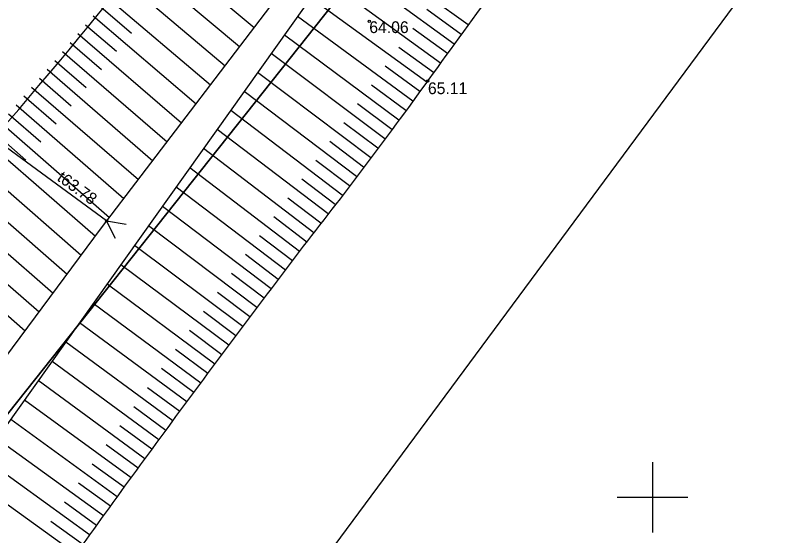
# Model space of a CAD drawing. Extents: x 616607 to 617499, y 408385 to 409695.
# Drawn here: x 617272.92 to 617306.12, y 409448.38 to 409470.48 of the extents above; entities that cross this region are included whole.
import ezdxf

# ---------------------------------------------------------------- set-up
doc = ezdxf.new("R2010")
doc.units = 0
for name, color, linetype in [('DREN_ELEM_####_####_#', 7, 'Continuous'), ('DREN_VADP_####_####_#', 7, 'Continuous'), ('DREN_VADP_####_TKST_#', 7, 'Continuous'), ('GEOD_ELEM_####_####_#', 7, 'Continuous'), ('HIDG_GRAV_####_####_#', 7, 'Continuous'), ('RAMI_UZMR_####_####_#', 7, 'Continuous'), ('RELJ_AATZ_####_TKST_#', 7, 'Continuous'), ('RELJ_ELEM_####_####_#', 7, 'Continuous'), ('RELJ_NOGA_####_####_#', 7, 'Continuous'), ('ROBZ_PROJ_####_####_#', 7, 'Continuous'), ('ROBZ_UZMR_####_####_#', 7, 'Continuous')]:
    doc.layers.add(name, color=color, linetype=linetype)

# ---------------------------------------------------------------- blocks, each defined once
blk = doc.blocks.new('PKT')
at = {"layer": 'RELJ_ELEM_####_####_#'}
blk.add_circle((0, 0), 0.05, dxfattribs=at)
blk = doc.blocks.new('DRIZVA')
at = {"layer": 'DREN_ELEM_####_####_#'}
blk.add_lwpolyline([(0.75, -0.375), (0, 0), (0.75, 0.375)], dxfattribs=at)
blk = doc.blocks.new('KRUSTS')
at = {"layer": 'GEOD_ELEM_####_####_#'}
for p, q in [((0, 1.5), (0, 0)), ((-1.5, 0), (0, 0)), ((0, 0), (0, -1.5)), ((0, 0), (1.5, 0))]:
    blk.add_line(p, q, dxfattribs=at)

msp = doc.modelspace()

# ---------------------------------------------------------------- linework, layer by layer
at = {"layer": 'DREN_VADP_####_####_#'}
msp.add_lwpolyline([(617276.789, 409461.747), (617266.774, 409469.076)], dxfattribs=at)
at = {"layer": 'HIDG_GRAV_####_####_#'}
for points in [[(617196.049, 409072.553), (617193.886, 409072.979), (617195.921, 409087.874), (617195.921, 409087.874), (617199.518, 409112.516), (617194.569, 409134.842), (617162.019, 409207.474), (617151.93, 409229.107), (617149.428, 409241.28), (617152.359, 409253.938), (617188.564, 409303.055), (617197.968, 409312.659), (617223.456, 409346.169), (617232.567, 409363.51), (617247.671, 409422.509), (617276.576, 409461.456), (617285.007, 409472.526), (617327.765, 409527.3)], [(617198.671, 409072.074), (617200.929, 409072.435), (617202.532, 409075.622), (617201.237, 409087.874), (617202.422, 409112.516), (617197.415, 409136.544), (617162.613, 409207.758), (617153.021, 409229.447), (617150.525, 409241.262), (617153.298, 409253.658), (617189.431, 409302.264), (617198.754, 409312.12), (617224.478, 409345.652), (617234.105, 409363.027), (617250.009, 409421.44), (617285.914, 409471.848), (617328.6, 409526.531)]]:
    msp.add_lwpolyline(points, dxfattribs=at)
at = {"layer": 'RAMI_UZMR_####_####_#'}
msp.add_lwpolyline([(617101.571, 408748.246), (617213.472, 409074.039), (617215.883, 409140.56), (617165.121, 409241.478), (617252.137, 409353.424), (617269.572, 409425.099), (617332.631, 409510.312), (617439.945, 409622.037), (617425.373, 409635.959), (617242.079, 409440.82), (617216.614, 409355.716), (617136.613, 409246.751), (617191.828, 409115.62), (617145.545, 408952.8)], dxfattribs=at)
at = {"layer": 'RELJ_NOGA_####_####_#'}
for p, q in [((617278.791, 409473.527), (617283.066, 409469.978)), ((617292.163, 409470.078), (617287.288, 409473.608)), ((617278.15, 409472.76), (617282.445, 409469.162)), ((617291.576, 409469.268), (617286.674, 409472.822)), ((617277.506, 409471.995), (617281.825, 409468.347)), ((617290.989, 409468.458), (617286.059, 409472.034)), ((617276.86, 409471.232), (617281.208, 409467.537)), ((617290.402, 409467.649), (617285.476, 409471.233)), ((617276.536, 409470.851), (617277.845, 409469.735)), ((617291.869, 409469.673), (617290.402, 409470.735)), ((617276.211, 409470.47), (617276.211, 409470.471)), ((617276.211, 409470.47), (617280.591, 409466.727)), ((617289.812, 409466.841), (617284.911, 409470.44)), ((617275.886, 409470.09), (617275.886, 409470.09)), ((617275.886, 409470.09), (617277.205, 409468.96)), ((617292.163, 409470.078), (617292.163, 409470.077)), ((617275.561, 409469.711), (617275.56, 409469.711)), ((617275.561, 409469.711), (617279.979, 409465.924)), ((617289.218, 409466.037), (617284.349, 409469.652)), ((617291.282, 409468.863), (617289.808, 409469.932)), ((617291.869, 409469.673), (617291.87, 409469.672)), ((617275.235, 409469.331), (617275.235, 409469.332)), ((617275.235, 409469.331), (617276.566, 409468.188)), ((617290.695, 409468.053), (617289.215, 409469.127)), ((617291.576, 409469.268), (617291.577, 409469.267)), ((617274.909, 409468.953), (617274.908, 409468.953)), ((617274.909, 409468.953), (617279.362, 409465.113)), ((617288.621, 409465.235), (617283.785, 409468.86)), ((617291.282, 409468.863), (617291.283, 409468.863)), ((617274.582, 409468.574), (617274.582, 409468.574)), ((617274.582, 409468.574), (617275.924, 409467.414)), ((617290.107, 409467.245), (617288.633, 409468.322)), ((617290.989, 409468.458), (617290.99, 409468.458)), ((617274.255, 409468.196), (617274.255, 409468.196)), ((617274.255, 409468.196), (617278.75, 409464.31)), ((617288.02, 409464.435), (617283.212, 409468.055)), ((617290.695, 409468.053), (617290.696, 409468.053)), ((617273.928, 409467.818), (617273.928, 409467.818)), ((617273.928, 409467.818), (617275.282, 409466.644)), ((617273.601, 409467.44), (617273.6, 409467.44)), ((617273.601, 409467.44), (617278.139, 409463.507)), ((617289.515, 409466.439), (617288.049, 409467.52)), ((617290.402, 409467.649), (617290.403, 409467.648)), ((617273.273, 409467.062), (617273.273, 409467.062)), ((617273.273, 409467.062), (617274.64, 409465.874)), ((617287.418, 409463.637), (617282.642, 409467.254)), ((617290.107, 409467.245), (617290.108, 409467.244)), ((617272.945, 409466.685), (617272.944, 409466.685)), ((617272.945, 409466.685), (617277.524, 409462.7)), ((617288.92, 409465.635), (617287.463, 409466.72)), ((617289.812, 409466.841), (617289.813, 409466.841)), ((617286.813, 409462.84), (617282.069, 409466.45)), ((617289.515, 409466.439), (617289.516, 409466.438)), ((617272.617, 409466.308), (617273.998, 409465.106)), ((617289.218, 409466.037), (617289.219, 409466.036)), ((617272.288, 409465.931), (617276.914, 409461.899)), ((617288.321, 409464.835), (617286.873, 409465.92)), ((617271.96, 409465.554), (617273.355, 409464.338)), ((617286.208, 409462.044), (617281.492, 409465.639)), ((617288.92, 409465.635), (617288.92, 409465.635)), ((617271.631, 409465.177), (617276.309, 409461.096)), ((617287.719, 409464.036), (617286.282, 409465.122)), ((617288.621, 409465.235), (617288.621, 409465.234)), ((617285.601, 409461.249), (617280.911, 409464.824)), ((617288.321, 409464.835), (617288.321, 409464.834)), ((617270.974, 409464.423), (617275.711, 409460.29)), ((617288.02, 409464.435), (617288.021, 409464.434)), ((617284.995, 409460.454), (617280.33, 409464.008)), ((617287.116, 409463.238), (617285.688, 409464.322)), ((617287.719, 409464.036), (617287.719, 409464.036)), ((617270.316, 409463.67), (617275.113, 409459.484)), ((617286.511, 409462.442), (617285.091, 409463.522)), ((617287.418, 409463.637), (617287.418, 409463.636)), ((617284.39, 409459.658), (617279.745, 409463.188)), ((617287.116, 409463.238), (617287.116, 409463.238)), ((617269.659, 409462.916), (617274.515, 409458.679)), ((617285.905, 409461.647), (617284.494, 409462.722)), ((617286.813, 409462.84), (617286.814, 409462.84)), ((617283.785, 409458.862), (617279.16, 409462.366)), ((617286.511, 409462.442), (617286.511, 409462.442)), ((617269.002, 409462.162), (617273.921, 409457.878)), ((617286.208, 409462.044), (617286.209, 409462.044)), ((617285.298, 409460.851), (617283.895, 409461.921)), ((617268.345, 409461.408), (617273.326, 409457.077)), ((617283.182, 409458.064), (617278.571, 409461.539)), ((617285.905, 409461.647), (617285.905, 409461.647)), ((617284.692, 409460.056), (617283.297, 409461.119)), ((617285.601, 409461.249), (617285.602, 409461.248)), ((617282.581, 409457.265), (617277.979, 409460.708)), ((617285.298, 409460.851), (617285.299, 409460.851)), ((617284.995, 409460.454), (617284.996, 409460.453)), ((617284.087, 409459.26), (617282.697, 409460.316)), ((617284.692, 409460.056), (617284.693, 409460.056)), ((617281.982, 409456.464), (617277.393, 409459.885)), ((617283.483, 409458.463), (617282.098, 409459.51)), ((617284.39, 409459.658), (617284.39, 409459.658)), ((617281.385, 409455.662), (617276.808, 409459.064)), ((617284.087, 409459.26), (617284.087, 409459.26)), ((617282.881, 409457.665), (617281.499, 409458.703)), ((617283.785, 409458.862), (617283.786, 409458.861)), ((617283.483, 409458.463), (617283.483, 409458.463)), ((617280.789, 409454.858), (617276.22, 409458.239)), ((617283.182, 409458.064), (617283.182, 409458.064)), ((617282.281, 409456.865), (617280.903, 409457.895)), ((617280.195, 409454.054), (617275.637, 409457.419)), ((617282.881, 409457.665), (617282.881, 409457.665)), ((617281.683, 409456.063), (617280.308, 409457.085)), ((617282.581, 409457.265), (617282.581, 409457.264)), ((617282.281, 409456.865), (617282.281, 409456.864)), ((617279.602, 409453.249), (617275.05, 409456.596)), ((617281.982, 409456.464), (617281.983, 409456.463)), ((617281.087, 409455.26), (617279.715, 409456.277)), ((617281.683, 409456.063), (617281.684, 409456.063)), ((617279.009, 409452.443), (617274.467, 409455.778)), ((617280.492, 409454.456), (617279.123, 409455.469)), ((617281.385, 409455.662), (617281.386, 409455.661)), ((617281.087, 409455.26), (617281.087, 409455.26)), ((617278.419, 409451.637), (617273.883, 409454.958)), ((617280.789, 409454.858), (617280.79, 409454.858)), ((617279.898, 409453.652), (617278.532, 409454.659)), ((617280.492, 409454.456), (617280.492, 409454.456)), ((617277.829, 409450.829), (617273.295, 409454.131)), ((617280.195, 409454.054), (617280.196, 409454.054)), ((617279.305, 409452.846), (617277.941, 409453.848)), ((617279.898, 409453.652), (617279.898, 409453.652)), ((617277.24, 409450.02), (617272.711, 409453.312)), ((617279.602, 409453.249), (617279.602, 409453.249)), ((617278.714, 409452.04), (617277.352, 409453.038)), ((617279.305, 409452.846), (617279.306, 409452.846)), ((617276.653, 409449.211), (617272.124, 409452.488)), ((617279.009, 409452.443), (617279.01, 409452.443)), ((617278.124, 409451.233), (617276.763, 409452.226)), ((617278.714, 409452.04), (617278.714, 409452.04)), ((617276.067, 409448.401), (617271.54, 409451.668)), ((617277.535, 409450.425), (617276.176, 409451.415)), ((617278.419, 409451.637), (617278.419, 409451.636)), ((617278.124, 409451.233), (617278.124, 409451.233)), ((617275.482, 409447.59), (617270.957, 409450.849)), ((617277.829, 409450.829), (617277.83, 409450.828)), ((617276.947, 409449.616), (617275.588, 409450.601)), ((617277.535, 409450.425), (617277.535, 409450.425)), ((617276.36, 409448.806), (617275.002, 409449.788)), ((617277.24, 409450.02), (617277.241, 409450.02)), ((617276.947, 409449.616), (617276.947, 409449.616)), ((617276.653, 409449.211), (617276.654, 409449.211)), ((617275.774, 409447.995), (617274.417, 409448.975)), ((617276.36, 409448.806), (617276.36, 409448.806)), ((617276.067, 409448.401), (617276.068, 409448.4))]:
    msp.add_line(p, q, dxfattribs=at)
for points in [[(617148.095, 409250.281), (617149.367, 409254.282), (617150.639, 409258.284), (617151.912, 409262.285), (617156.597, 409277.022), (617171.021, 409286.603), (617180.379, 409298.915), (617194.802, 409317.89), (617212.921, 409334.355), (617223.034, 409356.295), (617225.913, 409362.541), (617226.817, 409369.327), (617228.782, 409375.821), (617233.86, 409392.605), (617237.843, 409409.628), (617244.376, 409426.063), (617252.258, 409445.895), (617268.673, 409460.708), (617281.86, 409477.296), (617294.583, 409493.301), (617307.725, 409508.821), (617320.496, 409524.825), (617320.543, 409524.885), (617320.584, 409524.948), (617320.623, 409525.013), (617320.843, 409525.374), (617320.906, 409525.909), (617320.728, 409526.275), (617320.636, 409526.463), (617320.388, 409526.567), (617320.294, 409526.764), (617319.61, 409528.184), (617318.926, 409529.604), (617318.242, 409531.024)], [(617336.806, 409523.735), (617334.087, 409521.174), (617331.368, 409518.613), (617328.65, 409516.053), (617321.193, 409509.03), (617314.57, 409501.094), (617308.568, 409492.793), (617305.546, 409488.614), (617302.537, 409484.426), (617299.516, 409480.247), (617296.49, 409476.063), (617293.469, 409471.875), (617290.436, 409467.695), (617287.772, 409464.025), (617284.965, 409460.461), (617282.252, 409456.826), (617279.55, 409453.205), (617276.887, 409449.558), (617274.256, 409445.882), (617271.624, 409442.206), (617269.17, 409438.414), (617266.782, 409434.573), (617265.581, 409432.642), (617264.455, 409430.674), (617263.346, 409428.69), (617262.228, 409426.69), (617261.169, 409424.668), (617260.166, 409422.606), (617258.56, 409419.302), (617257.132, 409415.931), (617255.903, 409412.47), (617254.682, 409409.035), (617253.531, 409405.585), (617252.579, 409402.073), (617251.627, 409398.563), (617250.683, 409395.052), (617249.746, 409391.538), (617248.81, 409388.023), (617247.876, 409384.508), (617246.956, 409380.989), (617246.456, 409379.078), (617246.028, 409377.149), (617245.649, 409375.21), (617245.269, 409373.268), (617244.984, 409371.31), (617244.622, 409369.366), (617244.259, 409367.42), (617243.878, 409365.48), (617243.456, 409363.545), (617243.245, 409362.576), (617242.967, 409361.625), (617242.691, 409360.672), (617242.413, 409359.713), (617242.093, 409358.772), (617241.734, 409357.838), (617241.092, 409356.173), (617240.315, 409354.578), (617239.389, 409353.048), (617238.465, 409351.519), (617237.498, 409350.034), (617236.402, 409348.636), (617235.3, 409347.23), (617234.195, 409345.828), (617233.083, 409344.431), (617231.973, 409343.038), (617230.863, 409341.647), (617229.743, 409340.262), (617227.764, 409337.815), (617225.693, 409335.438), (617223.461, 409333.217), (617221.215, 409330.983), (617218.873, 409328.856), (617216.607, 409326.646), (617214.346, 409324.442), (617212.093, 409322.231), (617209.875, 409319.98), (617208.771, 409318.86), (617207.791, 409317.635), (617206.772, 409316.432), (617205.753, 409315.229), (617204.825, 409314.017), (617203.96, 409312.646), (617203.768, 409312.342), (617203.633, 409312.004), (617203.62, 409311.655), (617203.607, 409311.284), (617203.603, 409310.913), (617203.599, 409310.542), (617203.595, 409310.167), (617203.603, 409309.793), (617203.596, 409309.419), (617203.588, 409309.066), (617203.48, 409308.714), (617203.309, 409308.4), (617202.615, 409307.13), (617201.9, 409305.914), (617201.16, 409304.689), (617200.419, 409303.462), (617199.689, 409302.232), (617198.921, 409301.021), (617197.385, 409298.6), (617195.744, 409296.251), (617194.012, 409293.966), (617188.331, 409286.47), (617182.548, 409279.072), (617176.617, 409271.78), (617175.091, 409269.904), (617173.565, 409268.03), (617172.006, 409266.181), (617170.46, 409264.348), (617168.875, 409262.548), (617167.326, 409260.717), (617165.749, 409258.854), (617164.19, 409256.978), (617162.652, 409255.082), (617161.86, 409254.106), (617161.109, 409253.1), (617160.341, 409252.105), (617159.552, 409251.081), (617158.796, 409250.055), (617158.061, 409248.97), (617157.091, 409247.54), (617156.549, 409245.874), (617156.301, 409244.175), (617156.178, 409243.327), (617156.153, 409242.478), (617156.175, 409241.631), (617156.198, 409240.798), (617156.24, 409239.966), (617156.347, 409239.134), (617156.709, 409236.311), (617157.141, 409233.481), (617158.294, 409230.866), (617161.329, 409223.986), (617164.552, 409217.339), (617167.894, 409210.677), (617170.758, 409204.966), (617173.578, 409199.236), (617176.506, 409193.56), (617179.423, 409187.907), (617182.384, 409182.277), (617185.301, 409176.624), (617188.243, 409170.922), (617191.171, 409165.213), (617194.071, 409159.489), (617195.541, 409156.585), (617196.952, 409153.652), (617198.382, 409150.727), (617199.832, 409147.761), (617201.227, 409144.774), (617202.61, 409141.772), (617203.681, 409139.449), (617204.533, 409137.047), (617205.282, 409134.589), (617206.022, 409132.164), (617206.554, 409129.71), (617206.943, 409127.212), (617207.329, 409124.726), (617207.611, 409122.242), (617207.809, 409119.738), (617208.005, 409117.248), (617208.126, 409114.753), (617208.097, 409112.263), (617208.074, 409110.266), (617207.983, 409108.256), (617207.635, 409106.282), (617207.283, 409104.281), (617206.913, 409102.294), (617206.558, 409100.3), (617206.203, 409098.306), (617205.85, 409096.331), (617205.506, 409094.315), (617205.165, 409092.324), (617205.06, 409090.322), (617205.116, 409088.325), (617205.171, 409086.355), (617205.316, 409084.384), (617205.484, 409082.414), (617205.653, 409080.435), (617205.914, 409078.469), (617206.09, 409076.495), (617206.126, 409076.085), (617206.005, 409075.66), (617206.103, 409075.26)]]:
    msp.add_open_spline(points, degree=3, dxfattribs=at)
at = {"layer": 'ROBZ_PROJ_####_####_#'}
msp.add_lwpolyline([(617318.399, 409542.625), (617324.935, 409534.695), (617332.188, 409529.592), (617326.39, 409521.291), (617255.789, 409432.426), (617250.98, 409414.497), (617224.174, 409428.057)], dxfattribs=at)
at = {"layer": 'ROBZ_UZMR_####_####_#'}
msp.add_lwpolyline([(617232.583, 409073.745), (617196.025, 409075.262), (617200.886, 409119.423), (617196.507, 409136.07), (617150.138, 409230.13), (617148.652, 409247.272), (617201.229, 409318.934), (617233.453, 409357.938), (617244.928, 409391.934), (617250.98, 409414.497), (617255.789, 409432.426), (617326.39, 409521.291), (617332.188, 409529.592), (617332.358, 409529.835), (617335.391, 409534.333), (617341.051, 409533.641), (617349.913, 409536.856), (617370.73, 409556.7), (617378.749, 409547.935), (617381.343, 409545.1)], dxfattribs=at)

# ---------------------------------------------------------------- block references
at = {"layer": 'DREN_ELEM_####_####_#', "rotation": -36.19698632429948}
msp.add_blockref('DRIZVA', (617276.789, 409461.747), dxfattribs=at)
at = {"layer": 'GEOD_ELEM_####_####_#'}
msp.add_blockref('KRUSTS', (617300, 409450), dxfattribs=at)
at = {"layer": 'RELJ_ELEM_####_####_#'}
for p in [(617287.96, 409470.235), (617290.436, 409467.695), (617276.789, 409461.747)]:
    msp.add_blockref('PKT', p, dxfattribs=at)

# ---------------------------------------------------------------- texts
at = {"layer": 'DREN_VADP_####_TKST_#'}
msp.add_text('t63.78', height=0.5, rotation=323.803, dxfattribs=at).set_placement((617274.645, 409463.502))
at = {"layer": 'RELJ_AATZ_####_TKST_#'}
for s, p in [('64.06', (617287.96, 409469.735)), ('65.11', (617290.454, 409467.138))]:
    msp.add_text(s, height=0.5, dxfattribs=at).set_placement(p)

doc.saveas('drawing.dxf')
